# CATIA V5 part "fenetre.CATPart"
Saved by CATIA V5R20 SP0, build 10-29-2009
Part number: piece
Bounding box of the stored display mesh (mm): x -40 to 0, y 0 to 300, z 0 to 200
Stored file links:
  C:\Users\bensf\Desktop\bouthaina\fenetre.CATPart
  C:\Program Files (x86)\Dassault Systemes\B20\intel_a\startup\materials\French\Catalog.CATMaterial
  C:\Program Files (x86)\Dassault Systemes\B20\intel_a\startup\materials\wire.png
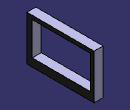
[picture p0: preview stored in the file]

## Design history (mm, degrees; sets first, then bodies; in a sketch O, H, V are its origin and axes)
Body1 (main body)
  Sketch1 on yz-plane, origin (0, 0, 0), H (0, 1, 0), V (0, 0, 1)
    line L1 (0, 0) -> (300, 0)
    line L2 (300, 0) -> (300, 200)
    line L3 (300, 200) -> (0, 200)
    line L4 (0, 200) -> (0, 0)
    length L3 = 300
    length L2 = 200
    horizontal: L1 H, L3 H
    vertical: L2 V, L4 V
  Pad1: profile Sketch1, direction (-1, 0, 0), length 40
  Sketch2 on start face of Pad1, origin (0, 0, 0), H (0, 1, 0), V (0, 0, 1)
    line L1 (23.7131, 183.2457) -> (284.4184, 183.2457)
    line L2 (284.4184, 183.2457) -> (284.4184, 35.6088)
    line L3 (284.4184, 35.6088) -> (23.7131, 35.6088)
    line L4 (23.7131, 35.6088) -> (23.7131, 183.2457)
    horizontal: L1 H, L3 H
    vertical: L2 V, L4 V
  Pocket1: profile Sketch2, direction (-1, 0, 0), length 40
